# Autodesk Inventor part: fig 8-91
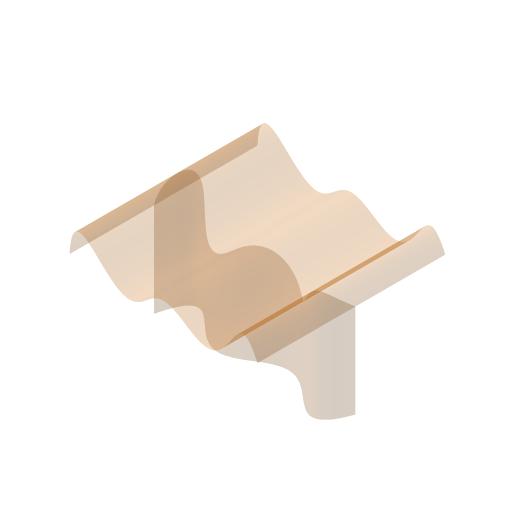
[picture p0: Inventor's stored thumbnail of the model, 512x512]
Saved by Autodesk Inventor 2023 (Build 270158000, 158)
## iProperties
Part Number: fig 8-91
Document SubType Name: Modeling
Created: 2003-08
Designer: Owner
Manufacturer: Standard
Standards Organization: Custom
Density: 1 g/cm^3
Material: Generic
Appearance: Default
Control State: 0
Master: False
Checked Out: False
Shininess: 64.0
Length Units: 11269
Angle Units: 11279
Time Units: 11290
Mass Units: 11283
Length Display Precision: 3
Angle Display Precision: 2
Compacted: True
Density: 0.0
Volumn: 0.0
Area: 0.0
PropertySet Name: Model Information
Author: Owner
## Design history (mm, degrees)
sketch "Sketch1"
  geometry: 7 further points
  constraints: 7 other
  dimensions: "d0" = 80 horizontal distance of point (40, 1.742) point (-40, -4.065); "d1" = 40 horizontal distance of point (0, 0) point (-40, -4.065)
extrude_surface "ExtrusionSrf1" sketch "Sketch1" dims "d2" = 80, "d3" = 0
sketch "Sketch2"
  geometry: L1 (40, 0)-(40, -40) reference; L2 (-40, 0)-(-40, -40) reference; 7 further points
  constraints: 2 point on line, 7 other
extrude_surface "ExtrusionSrf2" sketch "Sketch2" dims "d4" = 80, "d5" = 0
sketch "Sketch3"
  geometry: 2 further points
  constraints: 4 other
sketch "Sketch4"
  geometry: L1 (52.956, 12.425)-(-10.974, 12.425); A1 r 27.841 centre (-10.974, -15.416) between (-10.974, 12.425) and (-7.259, -43.008)
  constraints: 2 end point, 2 point on circle, 1 centre point, 1 horizontal, 1 tangent
feature "Trim1"
body "Srf1"
body "Srf2"
